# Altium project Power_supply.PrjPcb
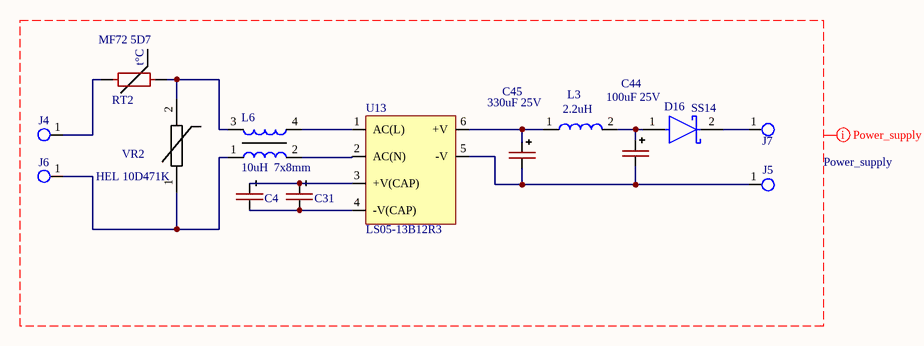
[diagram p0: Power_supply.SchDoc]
1 sheet, 14 parts. Net scope: global (net labels, ports and power ports of the same name join across sheets).
Board file: Power_supply.PcbDoc

## Sheet Power_supply.SchDoc
size A3; SheetNumber: 1; SheetTotal: 1; SPICEModelCacheNLVBOJOE: <root> / <DocumentId>NLVBOJOE</DocumentId> / </root>

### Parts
C4  6.8uF 450V  [CAPPOL_10x13]  (value not drawn)
C31  6.8uF 450V  [CAPPOL_10x13]  (value not drawn)
C44  100uF 25V  [CAP_A765EB_KEM-L]
C45  330uF 25V  [CAP_A765EB_KEM-L]
D16  SS14  [DO-214-AC]
J4  Pad_CONN 3.5mm  [Pad_conn_3.5x5mm]  (value not drawn)
J5  Pad_CONN 3.5mm  [Pad_conn_3.5x5mm]  (value not drawn)
J6  Pad_CONN 3.5mm  [Pad_conn_3.5x5mm]  (value not drawn)
J7  Pad_CONN 3.5mm  [Pad_conn_3.5x5mm]  (value not drawn)
L3  2.2uH  [Coil_4.5x4.5_mm]
L6  10uH  7x8mm  [Common Mode Choke Inductor  30mH]
RT2  MF72 5D7  [MF72 XD-7]
U13  LS05-13B12R3  [YLPTEC LS05-13B12R3]
VR2  HEL 10D471K  [HEL_7D561K]

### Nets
NetC4_1: C4.1(+) C31.1(+) U13.3(+V(CAP))
NetC4_2: C4.2(-) C31.2(-) U13.4(-V(CAP))
NetC44_1: C44.1(+) D16.1(A) L3.2
NetC44_2: C44.2(-) C45.2(-) J5.1 U13.5(-V)
NetC45_1: C45.1(+) L3.1 U13.6(+V)
NetD16_2: D16.2(C) J7.1
NetJ4_1: J4.1 RT2.2
NetJ6_1: J6.1 L6.1 VR2.1
NetL6_2: L6.2 U13.2(AC(N))
NetL6_3: L6.3 RT2.1 VR2.2
NetL6_4: L6.4 U13.1(AC(L))

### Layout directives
CompClassName: Power_supply: (no net found under the mark)

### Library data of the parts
C4 C31 = CAP-POLAR: 6.8uF 450V LOW ESR
C44 = CAP_POL_SMD: 100uF 25V SMD,D6.3xL5.4mm  RST100UF25V004​ / KNSCHA
C45 = CAP_POL_SMD: 330uF 25V SMD,D6.3xL7.7mm  KNSCHA
J4-J7 = Klema_15_A
L3 = Coil: 2.2uH 3A / 40mΩMAX  MPS MPL-AL4020-2R2
L6 = Drossel_Synphaze: 10uH  UU9.8 Common Mode Choke Inductor / https://www.aliexpress.com/item/1005010443177841.html?spm=a2g0o.productlist.main.2.581f7bb894iQm9&algo_pvid=ef88ecc3-47f4-4459-8795-a7f2bc477caf&algo_exp_id=ef88ecc3-47f4-4459-8795-a7f2bc477caf-1&pdp_ext_f=%7B%22order%22%3A%22121%22%2C%22spu_best_type%22%3A%22price%22%2C%22eval%22%3A%221%22%2C%22fromPage%22%3A%22search%22%7D&pdp_npi=6%40dis%21UAH%21205.26%2196.09%21%21%2127.70%2112.97%21%402103973d17954349978863633e10a8%2112000052425269179%21sea%21UA%214339914066%21X%211%210%21n_tag%3A-29919%3Bd%3A9b83968a%3Bm03_new_user%3A-29895&curPageLogUid=TjiBi6yV6N5C&utparam-url=scene%3Asearch%7Cquery_from%3A%7Cx_object_id%3A1005010443177841%7C_p_origin_prod%3A
RT2 = RES-TEMP
VR2 = MOV: Metal Oxide Varistor  HEL 10D471K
